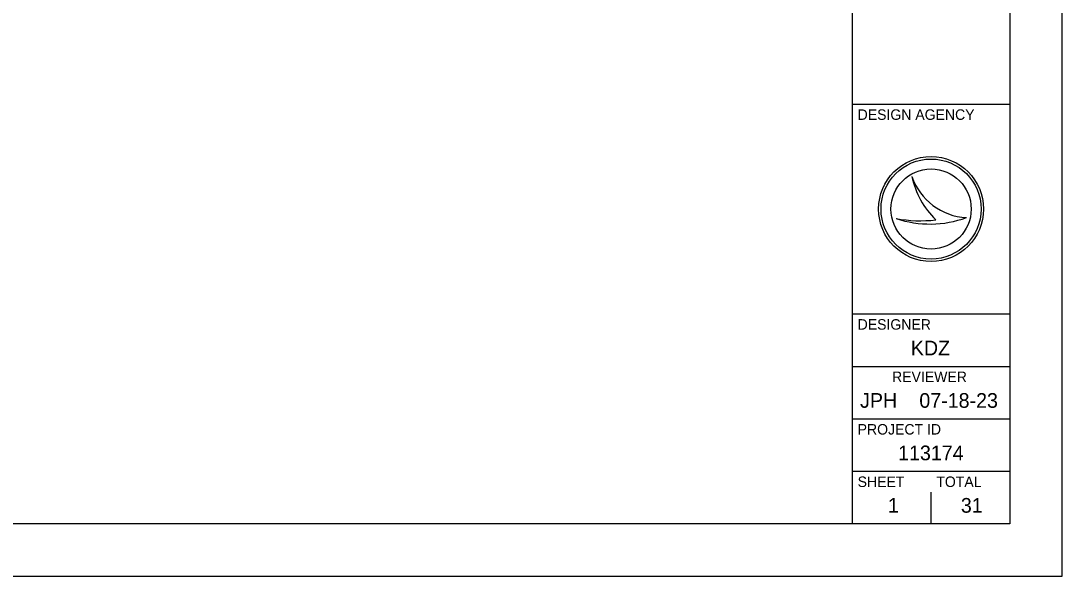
# Model space of a CAD drawing. Extents: x -8.2 to 34, y 0 to 22.
# Drawn here: x 24.07 to 34, y 0 to 5.29 of the extents above; entities that cross this region are included whole.
import ezdxf

# ---------------------------------------------------------------- set-up
doc = ezdxf.new("R2010")
doc.units = 0
for name, color, linetype in [('SH_Border', 7, 'Continuous'), ('SH_Cut_Line', 7, 'Continuous'), ('SH_Data', 7, 'Continuous')]:
    doc.layers.add(name, color=color, linetype=linetype)

msp = doc.modelspace()

# ---------------------------------------------------------------- linework, layer by layer
at = {"layer": 'SH_Border'}
for p, q in [((32, 0.5), (32, 21.5)), ((32, 4.5), (33.5, 4.5)), ((32, 2.5), (33.5, 2.5)), ((32, 2), (33.5, 2)), ((32, 1.5), (33.5, 1.5)), ((32, 1), (33.5, 1))]:
    msp.add_line(p, q, dxfattribs=at)
msp.add_lwpolyline([(1.5, 21.5), (33.5, 21.5), (33.5, 0.5), (1.5, 0.5)], close=True, dxfattribs=at)
at = {"layer": 'SH_Cut_Line'}
msp.add_lwpolyline([(0, 0), (34, 0), (34, 22), (0, 22)], close=True, dxfattribs=at)
at = {"layer": 'SH_Data'}
for p, q in [((32.5674, 3.8096), (32.5675, 3.8096)), ((32.75, 3.5), (32.75, 3.5)), ((32.4172, 3.4095), (32.4172, 3.4095)), ((33.0873, 3.4185), (33.0873, 3.4185)), ((32.75, 0.5), (32.75, 0.8)), ((32.375, 0.675), (32.375, 0.675))]:
    msp.add_line(p, q, dxfattribs=at)
for radius in [0.5, 0.4768, 0.4768, 0.3822]:
    msp.add_circle((32.75, 3.5), radius, dxfattribs=at)
for centre, radius, start, end in [((33.1159, 3.9976), 0.5798, 198.92567, 198.93195), ((33.3467, 3.9701), 0.7956, 191.63793, 191.64215), ((33.1159, 3.9976), 0.5798, 198.93195, 267.16574), ((33.3467, 3.9701), 0.7956, 191.64215, 226.09467), ((32.7394, 4.37), 1.0131, 251.45764, 290.08324), ((32.648, 4.6543), 1.2661, 259.49639, 259.49952), ((32.7394, 4.37), 1.0131, 251.45274, 251.45764), ((32.648, 4.6543), 1.2661, 259.49952, 276.66723)]:
    msp.add_arc(centre, radius, start, end, dxfattribs=at)

# ---------------------------------------------------------------- texts
for s, height, p in [('DESIGN AGENCY', 0.1, (32.05, 4.35)), ('DESIGNER', 0.1, (32.05, 2.35)), ('KDZ', 0.14, (32.5568, 2.105)), ('REVIEWER', 0.1, (32.3783, 1.85)), ('JPH', 0.14, (32.0731, 1.605)), ('07-18-23', 0.14, (32.6381, 1.605)), ('PROJECT ID', 0.1, (32.05, 1.35)), ('113174', 0.14, (32.4358, 1.105)), ('SHEET', 0.1, (32.05, 0.85)), ('TOTAL', 0.1, (32.8, 0.85)), ('1', 0.14, (32.3386, 0.605)), ('31', 0.14, (33.0342, 0.605))]:
    msp.add_text(s, height=height, dxfattribs=at).set_placement(p)

doc.saveas('drawing.dxf')
